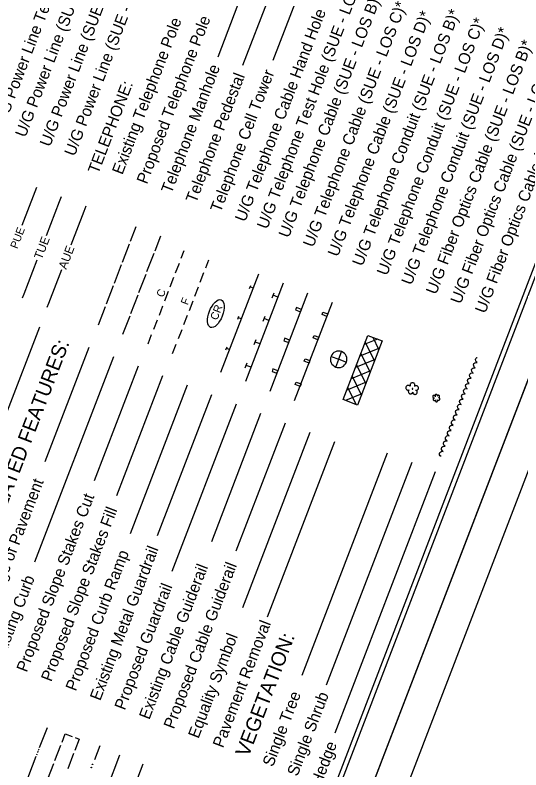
# Model space of a CAD drawing. Extents: x 1015221 to 1064345, y 619216 to 647967.
# Drawn here: x 1050556 to 1053572, y 626042 to 630539 of the extents above; entities that cross this region are included whole.
import ezdxf

# ---------------------------------------------------------------- set-up
doc = ezdxf.new("R2010")
doc.units = 0
for name, color, linetype in [('Default', 7, 'Continuous'), ('Sheet Cutting Line CELL', 7, 'Continuous'), ('Sheet Plot Border Inside CELL', 7, 'Continuous'), ('Sheet Plot Border Outside CELL', 7, 'Continuous'), ('Sheet Symbology CELL', 7, 'Continuous')]:
    doc.layers.add(name, color=color, linetype=linetype)

msp = doc.modelspace()

# ---------------------------------------------------------------- linework, layer by layer
at = {"layer": 'Default'}
for p, q in [((1056359.6, 634968.3), (1051618.2, 622627.5)), ((1052152.3, 631298.8), (1051764.4, 630289.1)), ((1052298.8, 631242.6), (1051912.8, 630238)), ((1052445.3, 631186.3), (1052092.9, 630269.1)), ((1050676.1, 629488), (1050686.4, 629514.8)), ((1050598.7, 629286.6), (1050676.1, 629488)), ((1050821.2, 629428.2), (1050832.9, 629458.5)), ((1050743.8, 629226.7), (1050821.2, 629428.2)), ((1050967.7, 629371.9), (1050979.4, 629402.3)), ((1050890.3, 629170.5), (1050967.7, 629371.9)), ((1051243.9, 629191.7), (1051277.7, 629279.6)), ((1051390.4, 629135.4), (1051424.2, 629223.3)), ((1051196.1, 629067.2), (1051238.3, 629177)), ((1051562.5, 629135.3), (1051544.5, 629088.4)), ((1051342.6, 629010.9), (1051384.8, 629120.7)), ((1050610.2, 628878.8), (1050687.6, 629080.3)), ((1051148.3, 628942.7), (1051190.5, 629052.5)), ((1051533.5, 629059.8), (1051511.4, 629002.3)), ((1051709, 629079), (1051691, 629032.1)), ((1050756.7, 628822.6), (1050834, 629024)), ((1051294.8, 628886.4), (1051337, 628996.2)), ((1051680, 629003.6), (1051657.9, 628946.1)), ((1051783.7, 628411.4), (1052008.8, 628997.4)), ((1051501, 628975.2), (1051479.2, 628918.5)), ((1051100.4, 628818.1), (1051142.6, 628928)), ((1051647.5, 628919), (1051625.7, 628862.2)), ((1052155.3, 628941.1), (1051930.2, 628355.1)), ((1051954.3, 628910.2), (1051961.3, 628928.5)), ((1051976.1, 628912.3), (1051957.8, 628919.3)), ((1050600.7, 628854.3), (1050610.2, 628878.8)), ((1051246.9, 628761.9), (1051289.1, 628871.7)), ((1051468.8, 628891.4), (1051446.8, 628834.2)), ((1052076.7, 628298.9), (1052301.8, 628884.8)), ((1052089, 628855), (1052100.3, 628884.3)), ((1052123.6, 628858.5), (1052094.6, 628869.6)), ((1050747.2, 628798), (1050756.7, 628822.6)), ((1051615.3, 628835.1), (1051593.3, 628778)), ((1052223.1, 628242.6), (1052448.3, 628828.5)), ((1051052.6, 628693.6), (1051094.8, 628803.5)), ((1051435.7, 628805.3), (1051414.3, 628749.7)), ((1051199.1, 628637.3), (1051241.3, 628747.2)), ((1051582.2, 628749), (1051560.8, 628693.4)), ((1051884, 628727.1), (1051891, 628745.4)), ((1051905.8, 628729.2), (1051887.5, 628736.2)), ((1052035.5, 628715.8), (1052046.8, 628745.1)), ((1052070.1, 628719.3), (1052041.2, 628730.5)), ((1050702.1, 628680.6), (1050509.5, 628179.2)), ((1051403.4, 628721.1), (1051382.1, 628665.8)), ((1051349, 628579.7), (1051370.4, 628635.4)), ((1051549.8, 628664.8), (1051528.6, 628609.5)), ((1051982.1, 628576.6), (1051993.3, 628605.9)), ((1052016.6, 628580.2), (1051987.7, 628591.3)), ((1052512.4, 628248.7), (1052659, 628630.3)), ((1052744.7, 628597.4), (1052598.1, 628215.8)), ((1052717.3, 628607.9), (1052638.1, 628575.7)), ((1052699.4, 628479.4), (1052644.6, 628592.6)), ((1052659, 628630.3), (1052744.7, 628597.4)), ((1052725.5, 628547.2), (1052691.3, 628617.9)), ((1050996.2, 628559.5), (1050733.9, 627876.6)), ((1051495.5, 628523.5), (1051516.9, 628579.1)), ((1051813.6, 628544), (1051820.6, 628562.3)), ((1051835.4, 628546.1), (1051817.1, 628553.1)), ((1052728.7, 628555.6), (1052611.9, 628507.6)), ((1051142.7, 628503.3), (1050672.4, 627279)), ((1052440, 628505.8), (1052485.7, 628488.2)), ((1052485.7, 628488.2), (1052503.3, 628534)), ((1052673.3, 628411.3), (1052618.5, 628524.8)), ((1051928.6, 628437.5), (1051939.9, 628466.8)), ((1052468.1, 628442.4), (1052485.7, 628488.2)), ((1052485.7, 628488.2), (1052531.5, 628470.6)), ((1052702.5, 628487.5), (1052585.9, 628439.9)), ((1052647.1, 628343.2), (1052592.5, 628457.1)), ((1053290, 628455.8), (1053292.6, 628462.7)), ((1053291, 628448.6), (1053290, 628455.8)), ((1053292.6, 628462.7), (1053298.6, 628467.2)), ((1053298.6, 628467.2), (1053304.9, 628469.4)), ((1053301.9, 628486.9), (1053304.6, 628493.8)), ((1053303, 628479.8), (1053301.9, 628486.9)), ((1053306, 628473.5), (1053303, 628479.8)), ((1053304.6, 628493.8), (1053310.5, 628498.3)), ((1053304.9, 628469.4), (1053311.6, 628468.4)), ((1053312.2, 628468.7), (1053306, 628473.5)), ((1053310.5, 628498.3), (1053311, 628498.5)), ((1051289.2, 628447), (1051027, 627764.4)), ((1051963.2, 628441), (1051934.2, 628452.1)), ((1052676.4, 628419.4), (1052559.8, 628372.1)), ((1053278, 628424.6), (1053280.7, 628431.6)), ((1053279, 628417.5), (1053278, 628424.6)), ((1053282.1, 628411.3), (1053279, 628417.5)), ((1053280.7, 628431.6), (1053286.6, 628436)), ((1053288.2, 628406.4), (1053282.1, 628411.3)), ((1053286.6, 628436), (1053292.9, 628438.2)), ((1053294.1, 628442.4), (1053291, 628448.6)), ((1053292.9, 628438.2), (1053299.7, 628437.3)), ((1053300.2, 628437.5), (1053294.1, 628442.4)), ((1051435.7, 628390.7), (1051160.7, 627674.8)), ((1052621.1, 628275.5), (1052566.3, 628389)), ((1053254.1, 628362.4), (1053256.8, 628369.3)), ((1053256.8, 628369.3), (1053262.7, 628373.8)), ((1053262.7, 628373.8), (1053269, 628376)), ((1053266, 628393.5), (1053268.7, 628400.5)), ((1053267.1, 628386.4), (1053266, 628393.5)), ((1053270.2, 628380.1), (1053267.1, 628386.4)), ((1053268.7, 628400.5), (1053274.6, 628404.9)), ((1053269, 628376), (1053275.8, 628375.1)), ((1053276.3, 628375.3), (1053270.2, 628380.1)), ((1053274.6, 628404.9), (1053280.9, 628407.1)), ((1053280.9, 628407.1), (1053287.7, 628406.2)), ((1051582.2, 628334.4), (1051241.9, 627448.7)), ((1052650.3, 628351.6), (1052533.7, 628304)), ((1052589.7, 628219), (1052540.2, 628320.8)), ((1053242.1, 628331.2), (1053244.8, 628338.2)), ((1053243.2, 628324.1), (1053242.1, 628331.2)), ((1053246.2, 628317.9), (1053243.2, 628324.1)), ((1053244.8, 628338.2), (1053250.7, 628342.7)), ((1053250.7, 628342.7), (1053257, 628344.9)), ((1053255.1, 628355.2), (1053254.1, 628362.4)), ((1053258.2, 628349), (1053255.1, 628355.2)), ((1053257, 628344.9), (1053263.8, 628343.9)), ((1053264.3, 628344.1), (1053258.2, 628349)), ((1051727.3, 628277.3), (1051404.2, 627436.2)), ((1052624.2, 628283.5), (1052525.6, 628243.6)), ((1053218.2, 628269), (1053220.9, 628275.9)), ((1053220.9, 628275.9), (1053226.8, 628280.4)), ((1053226.8, 628280.4), (1053233.1, 628282.6)), ((1053230.2, 628300.1), (1053232.8, 628307.1)), ((1053231.2, 628293), (1053230.2, 628300.1)), ((1053234.3, 628286.8), (1053231.2, 628293)), ((1053232.8, 628307.1), (1053238.8, 628311.5)), ((1053233.1, 628282.6), (1053239.9, 628281.7)), ((1053240.4, 628281.9), (1053234.3, 628286.8)), ((1053238.8, 628311.5), (1053245.1, 628313.7)), ((1053245.1, 628313.7), (1053251.9, 628312.8)), ((1053252.4, 628313), (1053246.2, 628317.9)), ((1052598.1, 628215.8), (1052512.4, 628248.7)), ((1052516.8, 628247), (1052514, 628252.7)), ((1053206.2, 628237.9), (1053208.9, 628244.8)), ((1053207.3, 628230.7), (1053206.2, 628237.9)), ((1053210.4, 628224.5), (1053207.3, 628230.7)), ((1053208.9, 628244.8), (1053214.8, 628249.3)), ((1053214.8, 628249.3), (1053221.1, 628251.5)), ((1053219.3, 628261.9), (1053218.2, 628269)), ((1053222.3, 628255.6), (1053219.3, 628261.9)), ((1053221.1, 628251.5), (1053227.9, 628250.5)), ((1053228.4, 628250.8), (1053222.3, 628255.6)), ((1051873.8, 628221), (1051490.5, 627223.2)), ((1053185, 628182.6), (1053190.9, 628187)), ((1053190.9, 628187), (1053197.2, 628189.2)), ((1053194.3, 628206.7), (1053197, 628213.7)), ((1053195.3, 628199.6), (1053194.3, 628206.7)), ((1053198.4, 628193.4), (1053195.3, 628199.6)), ((1053197, 628213.7), (1053202.9, 628218.1)), ((1053197.2, 628189.2), (1053204, 628188.3)), ((1053204.5, 628188.5), (1053198.4, 628193.4)), ((1053202.9, 628218.1), (1053209.2, 628220.3)), ((1053209.2, 628220.3), (1053216, 628219.4)), ((1053216.5, 628219.6), (1053210.4, 628224.5)), ((1052020.3, 628164.8), (1051726.8, 627400.8)), ((1053170.4, 628144.5), (1053173, 628151.4)), ((1053171.4, 628137.3), (1053170.4, 628144.5)), ((1053173, 628151.4), (1053179, 628155.9)), ((1053179, 628155.9), (1053185.3, 628158.1)), ((1053182.3, 628175.6), (1053185, 628182.6)), ((1053183.4, 628168.5), (1053182.3, 628175.6)), ((1053186.4, 628162.3), (1053183.4, 628168.5)), ((1053185.3, 628158.1), (1053192.1, 628157.2)), ((1053192.6, 628157.4), (1053186.4, 628162.3)), ((1052166.8, 628108.5), (1051873.3, 627344.6)), ((1053155, 628093.6), (1053161.3, 628095.8)), ((1053158.4, 628113.3), (1053161.1, 628120.3)), ((1053159.5, 628106.2), (1053158.4, 628113.3)), ((1053162.5, 628100), (1053159.5, 628106.2)), ((1053161.1, 628120.3), (1053167, 628124.8)), ((1053161.3, 628095.8), (1053168.1, 628094.9)), ((1053168.6, 628095.1), (1053162.5, 628100)), ((1053167, 628124.8), (1053173.3, 628127)), ((1053174.5, 628131.1), (1053171.4, 628137.3)), ((1053173.3, 628127), (1053180.1, 628126)), ((1053180.6, 628126.3), (1053174.5, 628131.1)), ((1052313.3, 628052.2), (1051911.9, 627007.6)), ((1053134.5, 628051.1), (1053137.2, 628058)), ((1053135.5, 628044), (1053134.5, 628051.1)), ((1053137.2, 628058), (1053143.1, 628062.5)), ((1053143.1, 628062.5), (1053149.4, 628064.7)), ((1053146.5, 628082.2), (1053149.1, 628089.2)), ((1053147.5, 628075.1), (1053146.5, 628082.2)), ((1053150.6, 628068.9), (1053147.5, 628075.1)), ((1053149.1, 628089.2), (1053155, 628093.6)), ((1053149.4, 628064.7), (1053156.2, 628063.8)), ((1053156.7, 628064), (1053150.6, 628068.9)), ((1053122.5, 628020), (1053125.2, 628026.9)), ((1053123.6, 628012.8), (1053122.5, 628020)), ((1053126.6, 628006.6), (1053123.6, 628012.8)), ((1053125.2, 628026.9), (1053131.1, 628031.4)), ((1053132.8, 628001.7), (1053126.6, 628006.6)), ((1053131.1, 628031.4), (1053137.4, 628033.6)), ((1053138.6, 628037.7), (1053135.5, 628044)), ((1053137.4, 628033.6), (1053144.2, 628032.6)), ((1053144.7, 628032.9), (1053138.6, 628037.7)), ((1052459.8, 627995.9), (1052058.4, 626951.3)), ((1053098.6, 627957.7), (1053101.3, 627964.7)), ((1053101.3, 627964.7), (1053107.2, 627969.1)), ((1053107.2, 627969.1), (1053113.5, 627971.3)), ((1053110.6, 627988.8), (1053113.2, 627995.8)), ((1053111.6, 627981.7), (1053110.6, 627988.8)), ((1053114.7, 627975.5), (1053111.6, 627981.7)), ((1053113.2, 627995.8), (1053119.2, 628000.2)), ((1053113.5, 627971.3), (1053120.3, 627970.4)), ((1053120.8, 627970.6), (1053114.7, 627975.5)), ((1053119.2, 628000.2), (1053125.5, 628002.4)), ((1053125.5, 628002.4), (1053132.3, 628001.5)), ((1052775.2, 627930), (1052265.5, 626603.4)), ((1053086.7, 627926.6), (1053089.3, 627933.5)), ((1053087.7, 627919.5), (1053086.7, 627926.6)), ((1053090.8, 627913.2), (1053087.7, 627919.5)), ((1053089.3, 627933.5), (1053095.2, 627938)), ((1053095.2, 627938), (1053101.5, 627940.2)), ((1053099.7, 627950.6), (1053098.6, 627957.7)), ((1053102.7, 627944.4), (1053099.7, 627950.6)), ((1053101.5, 627940.2), (1053108.3, 627939.3)), ((1053108.8, 627939.5), (1053102.7, 627944.4)), ((1052921.7, 627873.7), (1052412, 626547.2)), ((1053096.9, 627908.4), (1053090.8, 627913.2)), ((1053062, 627817.6), (1052463.5, 626259.8)), ((1050702.1, 626174.8), (1050748.4, 626295.5)), ((1050696.4, 626160.1), (1050699.3, 626167.5)), ((1050793.8, 626097.8), (1050828.9, 626189.4)), ((1050597.9, 625903.8), (1050682.4, 626123.5)), ((1050685.2, 626130.8), (1050688, 626138.2)), ((1050690.8, 626145.5), (1050693.6, 626152.8)), ((1050904.8, 626139), (1050869.6, 626047.5)), ((1051178.9, 626130), (1051096.5, 625915.4)), ((1050751.5, 625988), (1050786.7, 626079.5)), ((1051317.9, 626076.6), (1051235.5, 625862))]:
    msp.add_line(p, q, dxfattribs=at)
for points in [[(1052258.1, 628771.1), (1052263.7, 628785.7), (1052234.4, 628797), (1052228.8, 628782.3)], [(1052386.5, 628755.3), (1052392.1, 628769.9), (1052421.4, 628758.7), (1052415.8, 628744)], [(1052187.7, 628588), (1052193.4, 628602.6), (1052164.1, 628613.9), (1052158.5, 628599.2)], [(1052333, 628616.1), (1052338.7, 628630.8), (1052368, 628619.5), (1052362.3, 628604.9)], [(1052279.6, 628477), (1052285.2, 628491.6), (1052314.5, 628480.3), (1052308.9, 628465.7)], [(1052117.4, 628404.9), (1052123, 628419.5), (1052093.7, 628430.8), (1052088.1, 628416.1)], [(1052226.1, 628337.8), (1052231.7, 628352.4), (1052261, 628341.2), (1052255.4, 628326.5)]]:
    msp.add_lwpolyline(points, close=True, dxfattribs=at)
for points in [[(1052910.6, 628328), (1052908.4, 628330.1), (1052906.1, 628331.7), (1052903.1, 628332.5), (1052900.3, 628333), (1052897.1, 628332.5), (1052894.5, 628331.8), (1052891.6, 628330.3), (1052889.6, 628328.4), (1052887.6, 628325.9), (1052886.6, 628323.3), (1052885.8, 628320.3), (1052885.7, 628317.4), (1052886.2, 628314.5), (1052887.5, 628311.7), (1052889.2, 628309.4), (1052891.4, 628307.3), (1052893.9, 628306), (1052896.7, 628304.9), (1052899.6, 628304.4), (1052902.6, 628304.6), (1052905.6, 628305.4), (1052903.5, 628303.6), (1052902, 628301.2), (1052901.2, 628298.5), (1052900.8, 628295.7), (1052901.1, 628292.9), (1052901.9, 628290), (1052903.4, 628287.7), (1052905.2, 628285.4), (1052907.2, 628284), (1052910, 628282.6), (1052912.7, 628281.8), (1052915.5, 628282.1), (1052918.3, 628282.7), (1052920.7, 628283.7), (1052923.1, 628285.5), (1052925.1, 628287.4), (1052926.4, 628289.8), (1052927.4, 628292.4), (1052927.6, 628289.7), (1052928.6, 628287), (1052930.1, 628284.8), (1052932.2, 628282.6), (1052934.6, 628281.1), (1052937.1, 628279.8), (1052939.9, 628279.4), (1052942.6, 628279.6), (1052945.5, 628280.2), (1052947.9, 628281.2), (1052950.2, 628283), (1052952.1, 628285.3), (1052953.4, 628287.7), (1052954.1, 628290.4), (1052954.5, 628293.3), (1052953.9, 628296.1), (1052953, 628298.8), (1052951.5, 628301), (1052949.7, 628303.1), (1052947.3, 628304.6)], [(1052943.8, 628305), (1052946.8, 628304.2), (1052949.7, 628304), (1052952.6, 628304.6), (1052955.4, 628305.8), (1052957.7, 628307.6), (1052959.5, 628309.8), (1052960.9, 628312.6), (1052961.6, 628315.3), (1052961.8, 628318.3), (1052961.2, 628321.1), (1052960.3, 628323.8), (1052958.6, 628326.4), (1052956.4, 628328.3), (1052954, 628329.8), (1052951, 628330.7), (1052948.2, 628331.1), (1052945, 628330.6), (1052942.3, 628329.7), (1052940, 628327.9), (1052937.9, 628325.8), (1052939.3, 628328.6), (1052940.4, 628331.4), (1052940.5, 628334.4), (1052940.4, 628337.4), (1052939.5, 628340.4), (1052937.9, 628343), (1052935.8, 628345.4), (1052933.5, 628347), (1052930.7, 628348.4), (1052927.6, 628348.9), (1052924.6, 628349.1), (1052921.7, 628348.2), (1052918.9, 628347), (1052916.6, 628345.2), (1052914.3, 628342.8), (1052913, 628340.3), (1052911.9, 628337.4), (1052911.7, 628334.2), (1052912.2, 628331.3), (1052913, 628328.4)], [(1052923.6, 628313.7), (1052923.2, 628312.6), (1052923, 628311.3), (1052923.7, 628310.4), (1052924.7, 628309.7), (1052926, 628309.5), (1052927.2, 628310), (1052927.6, 628311.2), (1052927.8, 628312.5), (1052927.2, 628313.7), (1052926.2, 628314.4), (1052924.8, 628314.3), (1052923.6, 628313.7)], [(1053056.9, 628257.6), (1053054.9, 628257.3), (1053052.8, 628256.2), (1053050.9, 628254.9), (1053049.9, 628253), (1053049.4, 628250.8), (1053049.2, 628248.6), (1053050, 628246.3), (1053051.3, 628244.5), (1053053, 628243.1), (1053055.1, 628242.4), (1053057.3, 628242.2), (1053059.5, 628242.7), (1053061.6, 628243.8), (1053063.2, 628245.5), (1053064, 628247.5), (1053062.9, 628245.6), (1053062.2, 628243.6), (1053062.1, 628241.7), (1053062.6, 628239.5), (1053063.6, 628237.8), (1053065.1, 628236.5), (1053067, 628235.5), (1053069.1, 628235), (1053071.2, 628235.2), (1053073.2, 628236.1), (1053074.7, 628237.5), (1053075.9, 628239), (1053076.4, 628241.1), (1053076.5, 628243.1), (1053076, 628245.2), (1053075, 628247), (1053076.7, 628245.3), (1053078.6, 628244.2), (1053080.9, 628244), (1053082.9, 628244.2), (1053085.2, 628245), (1053086.7, 628246.4), (1053088.1, 628248.2), (1053088.6, 628250.3), (1053088.8, 628252.6), (1053088.3, 628254.8), (1053087, 628256.6), (1053085.3, 628258.2), (1053083.3, 628259), (1053081.2, 628259.5), (1053082.9, 628259.8), (1053085, 628261), (1053086.3, 628262.5), (1053087.4, 628264.4), (1053087.8, 628266.5), (1053087.6, 628268.6), (1053086.8, 628270.6), (1053085.4, 628272.1), (1053083.4, 628273.2), (1053081.4, 628273.9), (1053079.4, 628273.7), (1053077.5, 628273.1), (1053075.8, 628272.1), (1053074.1, 628270.5), (1053073.4, 628268.4), (1053074.1, 628270.5), (1053074.3, 628272.7), (1053073.7, 628274.6), (1053072.6, 628276.7), (1053071, 628277.9), (1053069, 628278.7), (1053066.9, 628279.2), (1053064.7, 628278.7), (1053063, 628277.7), (1053061.4, 628276), (1053060.3, 628274.1), (1053060.2, 628272.2), (1053060.3, 628269.8), (1053061.3, 628268.1), (1053062.7, 628266.6)], [(1053062.4, 628265.7), (1053062.2, 628267.8), (1053061, 628269.9), (1053059.6, 628271.4), (1053057.7, 628272.5), (1053055.7, 628273.2), (1053053.3, 628273.2), (1053051.4, 628272.6), (1053049.4, 628271.7), (1053048.1, 628269.9), (1053047, 628268), (1053046.5, 628265.8), (1053046.7, 628263.8), (1053047.5, 628261.5), (1053048.9, 628260), (1053050.7, 628258.6), (1053052.7, 628257.8), (1053054.9, 628257.3), (1053057, 628257.8)], [(1050836, 626207.7), (1050855.2, 626257.7), (1050896.7, 626241.7)], [(1050915, 626234.7), (1050938.1, 626225.8), (1050911.8, 626157.3)], [(1051031.5, 626104.5), (1051063.6, 626188.2)]]:
    msp.add_lwpolyline(points, dxfattribs=at)
for start, end in [(158.9774, 248.9819), (68.9774, 158.9819), (338.9774, 68.9819), (248.9774, 338.9819)]:
    msp.add_arc((1052485.7, 628488.2), 49, start, end, dxfattribs=at)
for centre, major_axis, ratio in [((1051753.1, 628760.4), (31.6, 82.1), 0.462467), ((1051017.8, 626075.2), (-1.44, 0.55), 0.938496), ((1051010.6, 626056.3), (-1.44, 0.55), 0.938496)]:
    msp.add_ellipse(centre, major_axis=major_axis, ratio=ratio, dxfattribs=at)
at = {"layer": 'Sheet Cutting Line CELL'}
msp.add_line((1051028.5, 621633.8), (1055860.2, 634209.5), dxfattribs=at)
at = {"layer": 'Sheet Plot Border Inside CELL'}
msp.add_lwpolyline([(1050898.2, 621795.3), (1055679.6, 634240.3), (1047800.3, 637267.6), (1043018.9, 624822.5)], close=True, dxfattribs=at)
at = {"layer": 'Sheet Plot Border Outside CELL'}
msp.add_lwpolyline([(1051028.5, 621633.8), (1055860.2, 634209.5), (1047645.6, 637365.6), (1042813.9, 624789.8)], close=True, dxfattribs=at)
at = {"layer": 'Sheet Symbology CELL'}
msp.add_lwpolyline([(1047783.5, 637166.9), (1043479.8, 625965.2), (1051313.4, 622955.5), (1055617.1, 634157.2)], close=True, dxfattribs=at)

# ---------------------------------------------------------------- texts
at = {"layer": 'Default'}
for s, height, p in [('U/G Power Line Test Hole (SUE - LOS A)*', 68.654, (1050485.4, 629859.5)), ('U/G Power Cable Hand Hole', 68.654, (1050200, 629969.1)), ('U/G Power Line (SUE - LOS B)*', 68.654, (1050617.7, 629806.3)), ('U/G Power Line (SUE - LOS C)*', 68.654, (1050764.4, 629750.2)), ('U/G Power Line (SUE - LOS D)*', 68.654, (1050911, 629694.1)), ('U/G Telephone Test Hole (SUE - LOS A)*', 68.654, (1052059.7, 629259.3)), ('U/G Telephone Cable (SUE - LOS B)*', 68.654, (1052188, 629207.7)), ('U/G Telephone Cable (SUE - LOS C)*', 68.654, (1052334.5, 629151.4)), ('U/G Telephone Cable Hand Hole', 68.654, (1051928, 629303)), ('U/G Telephone Conduit (SUE - LOS B)*', 68.654, (1052627.5, 629038.9)), ('Existing Telephone Pole', 68.654, (1051195.5, 629584.3)), ('Proposed Telephone Pole', 68.654, (1051342, 629528.1)), ('U/G Telephone Cable (SUE - LOS D)*', 68.654, (1052481, 629095.1)), ('U/G Telephone Conduit (SUE - LOS C)*', 68.654, (1052774, 628982.6)), ('U/G Telephone Conduit (SUE - LOS D)*', 68.654, (1052920.4, 628926.3)), ('U/G Fiber Optics Cable (SUE - LOS B)*', 68.654, (1053066.9, 628870)), ('U/G Fiber Optics Cable (SUE - LOS C)*', 68.654, (1053213.4, 628813.7)), ('U/G Fiber Optics Cable (SUE - LOS D)*', 68.654, (1053359.9, 628757.5)), ('Telephone Manhole', 68.654, (1051488.5, 629471.8)), ('Telephone Cell Tower', 68.654, (1051781.5, 629359.3)), ('Telephone Pedestal', 68.654, (1051635, 629415.5)), ('TELEPHONE:', 68.65, (1051051.8, 629588.6)), ('PUE', 47.08, (1050568.9, 629143.4)), ('TUE', 51.39, (1050714.9, 629079.1)), ('AUE', 51.39, (1050860.6, 629020.9)), ('C', 46.5, (1051439.9, 628854.2)), ('F', 46.5, (1051585.2, 628808.4)), ('CR', 47.08, (1051761.5, 628717.6)), ('ROADS AND RELATED FEATURES:', 86.308, (1050189.5, 626784.5)), ('Existing Edge of Pavement', 68.654, (1050332.4, 626732.2)), ('Proposed Slope Stakes Cut', 68.654, (1050625.4, 626619.6)), ('Proposed Slope Stakes Fill', 68.654, (1050771.9, 626563.3)), ('Existing Metal Guardrail', 68.654, (1051063.5, 626449.9)), ('Proposed Curb Ramp', 68.654, (1050918.3, 626507)), ('Existing Cable Guiderail', 68.654, (1051356.4, 626337.5)), ('Proposed Cable Guiderail', 68.654, (1051502.9, 626281.2)), ('Existing Curb', 68.654, (1050478.9, 626675.9)), ('Proposed Guardrail', 68.654, (1051209.9, 626393.8)), ('Pavement Removal', 68.654, (1051795.9, 626168.7)), ('Equality Symbol', 68.654, (1051649.4, 626225)), ('VEGETATION:', 86.308, (1051947.6, 626114)), ('Single Tree', 68.654, (1052093.2, 626055.8)), ('Single Shrub', 68.654, (1052239.6, 625999.5)), ('Hedge', 68.65, (1052379.9, 625943.3))]:
    msp.add_text(s, height=height, rotation=68.983, dxfattribs=at).set_placement(p)

doc.saveas('drawing.dxf')
